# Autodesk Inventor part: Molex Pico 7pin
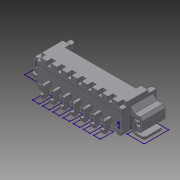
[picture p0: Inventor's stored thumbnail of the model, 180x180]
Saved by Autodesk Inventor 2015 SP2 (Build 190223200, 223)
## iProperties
Created: 2015-09
Part Number: Molex Pico 7pin
Material: Allgemein
Document SubType Name: Modeling
Designer: rYan
Density: 1 g/cm^3
Appearance: Vorgabe
Author: rYan
Author: me
Title: 532610771
Sending System: PRO/ENGINEER BY PARAMETRIC TECHNOLOGY CORPORATION, 2011490
Preprocessor: PRO/ENGINEER BY PARAMETRIC TECHNOLOGY CORPORATION, 2011490
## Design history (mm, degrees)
node "5326107711"
  sketch "3D-Skizze1"
node "Volumenkörper1"
node "Basis1"
